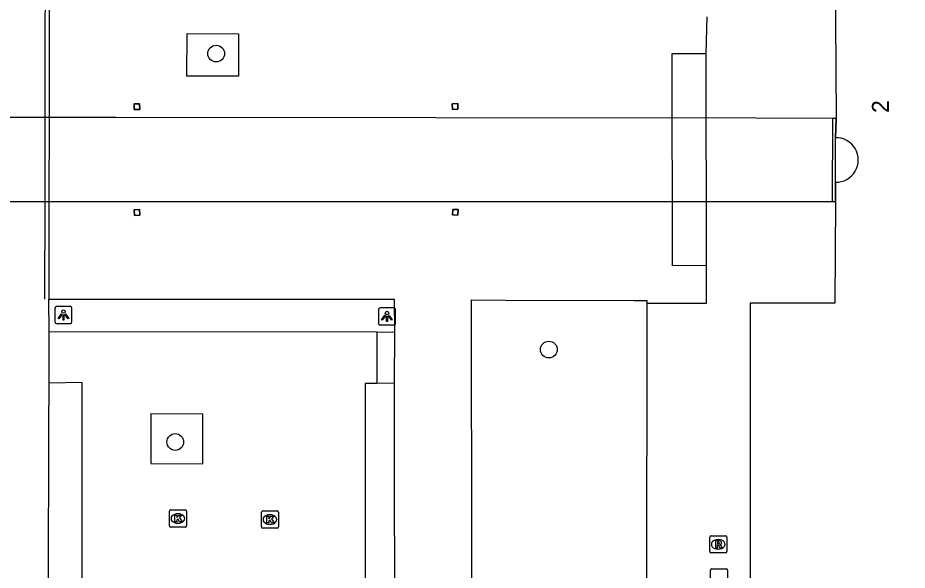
# Model space of a CAD drawing. Extents: x 161477 to 163040, y 383680 to 384868.
# Drawn here: x 161812.2 to 161864.2, y 384291 to 384323.3 of the extents above; entities that cross this region are included whole.
import ezdxf

# ---------------------------------------------------------------- set-up
doc = ezdxf.new("R2010")
doc.units = 0
for name, color, linetype in [('IMGEO_Boom', 7, 'Continuous'), ('IMGEO_Dek', 7, 'Continuous'), ('IMGEO_Kolk', 7, 'Continuous'), ('IMGEO_Lichtpunt', 7, 'Continuous'), ('IMGEO_Lijnafwatering', 7, 'Continuous'), ('IMGEO_Pand', 7, 'Continuous'), ('IMGEO_Pand_nummerreeks', 7, 'Continuous'), ('IMGEO_Parkeervlak_open', 7, 'Continuous'), ('IMGEO_Pijler', 7, 'Continuous'), ('IMGEO_Rijbaan_lokaal_open', 7, 'Continuous'), ('IMGEO_Rioolput', 7, 'Continuous'), ('IMGEO_Voetpad_gesloten', 7, 'Continuous'), ('IMGEO_Voetpad_op_trap', 7, 'Continuous'), ('IMGEO_Voetpad_open', 7, 'Continuous')]:
    doc.layers.add(name, color=color, linetype=linetype)

msp = doc.modelspace()

# ---------------------------------------------------------------- linework, layer by layer
at = {"layer": 'IMGEO_Boom'}
for centre in [(161823.823, 384321.172), (161843.275, 384303.878), (161821.432, 384298.478)]:
    msp.add_circle(centre, 0.489, dxfattribs=at)
at = {"layer": 'IMGEO_Dek'}
msp.add_lwpolyline([(161859.88, 384317.389), (161855.377, 384317.394), (161817.96, 384317.433), (161817.483, 384317.433), (161815.892, 384317.434), (161810.287, 384317.441), (161807.922, 384317.443), (161801.84, 384317.449), (161797.149, 384317.454), (161796.557, 384317.455), (161796.614, 384312.532), (161797.345, 384312.53), (161799.896, 384312.527), (161807.923, 384312.527), (161808.422, 384312.528), (161810.306, 384312.528), (161815.872, 384312.528), (161817.492, 384312.528), (161817.958, 384312.528), (161855.375, 384312.529), (161859.867, 384312.53)], close=True, dxfattribs=at)
at = {"layer": 'IMGEO_Kolk'}
for p, q in [((161821.088, 384293.582), (161821.088, 384294.434)), ((161821.163, 384294.508), (161822.015, 384294.508)), ((161822.089, 384294.434), (161822.089, 384293.582)), ((161826.541, 384294.447), (161827.393, 384294.447)), ((161821.576, 384294.288), (161821.601, 384294.288)), ((161826.466, 384293.521), (161826.466, 384294.373)), ((161826.954, 384294.227), (161826.979, 384294.227)), ((161827.467, 384294.373), (161827.467, 384293.521)), ((161822.015, 384293.508), (161821.163, 384293.508)), ((161821.599, 384293.728), (161821.574, 384293.728)), ((161827.393, 384293.447), (161826.541, 384293.447)), ((161826.977, 384293.667), (161826.952, 384293.667))]:
    msp.add_line(p, q, dxfattribs=at)
for points in [[(161821.088, 384293.582), (161821.088, 384294.434)], [(161821.163, 384294.508), (161822.015, 384294.508)], [(161822.089, 384294.434), (161822.089, 384293.582)], [(161826.541, 384294.447), (161827.393, 384294.447)], [(161821.409, 384294.208), (161821.532, 384294.208), (161821.532, 384294.057), (161821.662, 384294.208), (161821.826, 384294.208), (161821.68, 384294.057), (161821.833, 384293.808), (161821.681, 384293.808), (161821.596, 384293.972), (161821.532, 384293.905), (161821.532, 384293.808), (161821.409, 384293.808), (161821.409, 384294.208)], [(161826.466, 384293.521), (161826.466, 384294.373)], [(161826.787, 384294.147), (161826.91, 384294.147), (161826.91, 384293.996), (161827.04, 384294.147), (161827.204, 384294.147), (161827.058, 384293.996), (161827.211, 384293.747), (161827.059, 384293.747), (161826.974, 384293.911), (161826.91, 384293.844), (161826.91, 384293.747), (161826.787, 384293.747), (161826.787, 384294.147)], [(161827.467, 384294.373), (161827.467, 384293.521)], [(161822.015, 384293.508), (161821.163, 384293.508)], [(161827.393, 384293.447), (161826.541, 384293.447)]]:
    msp.add_lwpolyline(points, dxfattribs=at)
for centre, start, end in [((161821.165, 384294.432), 91.552, 178.448), ((161821.165, 384294.432), 91.552, 178.448), ((161822.013, 384294.432), 1.552, 88.448), ((161822.013, 384294.432), 1.552, 88.448), ((161826.543, 384294.371), 91.552, 178.448), ((161826.543, 384294.371), 91.552, 178.448), ((161827.391, 384294.371), 1.552, 88.448), ((161827.391, 384294.371), 1.552, 88.448), ((161821.165, 384293.584), 181.552, 268.448), ((161821.165, 384293.584), 181.552, 268.448), ((161822.013, 384293.584), 271.552, 358.448), ((161822.013, 384293.584), 271.552, 358.448), ((161826.543, 384293.523), 181.552, 268.448), ((161826.543, 384293.523), 181.552, 268.448), ((161827.391, 384293.523), 271.552, 358.448), ((161827.391, 384293.523), 271.552, 358.448)]:
    msp.add_arc(centre, 0.0765, start, end, dxfattribs=at)
for centre, major_axis, ratio, start_param, end_param in [((161821.575, 384294.008), (-0.387, 0.002), 0.722429, 4.712389, 7.853982), ((161821.6, 384294.008), (-0.39, 0.002), 0.717154, 1.570796, 4.712389), ((161826.953, 384293.947), (-0.387, 0.002), 0.722429, 4.712389, 7.853982), ((161826.978, 384293.947), (-0.39, 0.002), 0.717154, 1.570796, 4.712389)]:
    msp.add_ellipse(centre, major_axis=major_axis, ratio=ratio, start_param=start_param, end_param=end_param, dxfattribs=at)
at = {"layer": 'IMGEO_Lichtpunt'}
for p, q in [((161815.298, 384306.394), (161814.49, 384306.394)), ((161815.298, 384306.394), (161814.49, 384306.394)), ((161814.396, 384306.299), (161814.396, 384305.492)), ((161814.396, 384306.299), (161814.396, 384305.492)), ((161815.392, 384305.492), (161815.392, 384306.299)), ((161815.392, 384305.492), (161815.392, 384306.299)), ((161833.313, 384306.216), (161833.313, 384305.409)), ((161833.313, 384306.216), (161833.313, 384305.409)), ((161834.215, 384306.311), (161833.407, 384306.311)), ((161834.215, 384306.311), (161833.407, 384306.311)), ((161834.309, 384305.409), (161834.309, 384306.216)), ((161834.309, 384305.409), (161834.309, 384306.216)), ((161814.49, 384305.398), (161815.298, 384305.398)), ((161814.49, 384305.398), (161815.298, 384305.398)), ((161833.407, 384305.315), (161834.215, 384305.315)), ((161833.407, 384305.315), (161834.215, 384305.315))]:
    msp.add_line(p, q, dxfattribs=at)
for points in [[(161814.77, 384305.963), (161814.809, 384305.935), (161814.621, 384305.673), (161814.583, 384305.7), (161814.77, 384305.963)], [(161814.872, 384305.915), (161814.919, 384305.915), (161814.919, 384305.593), (161814.872, 384305.593), (161814.872, 384305.915)], [(161814.982, 384305.935), (161815.02, 384305.962), (161815.207, 384305.7), (161815.168, 384305.672), (161814.982, 384305.935)], [(161833.687, 384305.88), (161833.726, 384305.852), (161833.538, 384305.59), (161833.5, 384305.617), (161833.687, 384305.88)], [(161833.789, 384305.832), (161833.836, 384305.832), (161833.836, 384305.51), (161833.789, 384305.51), (161833.789, 384305.832)], [(161833.899, 384305.852), (161833.937, 384305.879), (161834.124, 384305.617), (161834.085, 384305.589), (161833.899, 384305.852)]]:
    msp.add_lwpolyline(points, dxfattribs=at)
for centre in [(161814.895, 384306.097), (161833.812, 384306.014)]:
    msp.add_circle(centre, 0.0994, dxfattribs=at)
for centre, start, end in [((161814.49, 384306.299), 90, 180), ((161814.49, 384306.299), 90, 180), ((161815.298, 384306.299), 0, 90), ((161815.298, 384306.299), 0, 90), ((161833.407, 384306.216), 90, 180), ((161833.407, 384306.216), 90, 180), ((161834.215, 384306.216), 0, 90), ((161834.215, 384306.216), 0, 90), ((161814.49, 384305.492), 180, 270), ((161814.49, 384305.492), 180, 270), ((161815.298, 384305.492), 270, 0), ((161815.298, 384305.492), 270, 360), ((161833.407, 384305.409), 180, 270), ((161833.407, 384305.409), 180, 270), ((161834.215, 384305.409), 270, 0), ((161834.215, 384305.409), 270, 360)]:
    msp.add_arc(centre, 0.0946, start, end, dxfattribs=at)
at = {"layer": 'IMGEO_Lijnafwatering'}
for points in [[(161813.824, 384317.437), (161813.835, 384329.719)], [(161813.819, 384312.528), (161813.824, 384317.437)], [(161813.814, 384306.819), (161813.819, 384312.528)]]:
    msp.add_lwpolyline(points, dxfattribs=at)
at = {"layer": 'IMGEO_Pand'}
for points in [[(161852.559, 384329.203), (161860.001, 384329.128), (161860.002, 384328.971), (161860.071, 384317.389), (161860.03, 384316.258)], [(161860.03, 384313.658), (161860.049, 384312.53), (161860.003, 384306.592), (161855.053, 384306.595), (161855.033, 384267.359)]]:
    msp.add_lwpolyline(points, dxfattribs=at)
msp.add_arc((161860.068, 384314.958), 1.301, 268.3067, 91.6933, dxfattribs=at)
at = {"layer": 'IMGEO_Parkeervlak_open'}
for points in [[(161814.057, 384304.937), (161833.227, 384304.914)], [(161814.017, 384269.739), (161815.984, 384269.764), (161815.992, 384301.962), (161814.049, 384301.923)], [(161833.222, 384301.901), (161832.538, 384301.901), (161832.535, 384269.792), (161833.234, 384269.806)], [(161823.049, 384300.107), (161820.005, 384300.13), (161820.005, 384297.224), (161823.034, 384297.204), (161823.049, 384300.107)]]:
    msp.add_lwpolyline(points, dxfattribs=at)
at = {"layer": 'IMGEO_Pijler'}
for points in [[(161819.342, 384318.246), (161819.028, 384318.238), (161819.036, 384317.908), (161819.35, 384317.916)], [(161837.949, 384318.249), (161837.628, 384318.234), (161837.643, 384317.905), (161837.964, 384317.92)], [(161837.975, 384312.055), (161837.667, 384312.073), (161837.648, 384311.744), (161837.956, 384311.726)], [(161819.339, 384312.06), (161819.036, 384312.041), (161819.056, 384311.711), (161819.359, 384311.73)]]:
    msp.add_lwpolyline(points, close=True, dxfattribs=at)
at = {"layer": 'IMGEO_Rijbaan_lokaal_open'}
for points in [[(161814.035, 384329.719), (161814.06, 384323.352), (161814.051, 384317.437), (161814.043, 384312.528), (161814.034, 384306.822)], [(161814.057, 384304.937), (161814.034, 384306.822)], [(161814.049, 384301.923), (161814.057, 384304.937)], [(161814.017, 384269.739), (161814.02, 384280.045), (161814.015, 384290.015), (161814.031, 384299.293), (161814.049, 384301.923)]]:
    msp.add_lwpolyline(points, dxfattribs=at)
at = {"layer": 'IMGEO_Rioolput'}
for p, q in [((161852.682, 384292.073), (161852.682, 384292.925)), ((161852.757, 384292.999), (161853.609, 384292.999)), ((161853.683, 384292.925), (161853.683, 384292.073)), ((161853.17, 384292.779), (161853.195, 384292.779)), ((161853.609, 384291.999), (161852.757, 384291.999)), ((161853.193, 384292.219), (161853.168, 384292.219)), ((161852.725, 384290.135), (161852.725, 384290.987)), ((161852.8, 384291.061), (161853.652, 384291.061)), ((161853.726, 384290.987), (161853.726, 384290.135))]:
    msp.add_line(p, q, dxfattribs=at)
for points in [[(161852.682, 384292.073), (161852.682, 384292.925)], [(161852.757, 384292.999), (161853.609, 384292.999)], [(161853.683, 384292.925), (161853.683, 384292.073)], [(161853.271, 384292.697), (161853.019, 384292.699), (161853.019, 384292.299)], [(161853.019, 384292.299), (161853.143, 384292.299), (161853.143, 384292.461), (161853.154, 384292.461)], [(161853.197, 384292.618), (161853.143, 384292.618), (161853.143, 384292.537)], [(161853.143, 384292.537), (161853.195, 384292.537)], [(161853.201, 384292.432), (161853.272, 384292.299), (161853.412, 384292.299), (161853.347, 384292.425)], [(161853.609, 384291.999), (161852.757, 384291.999)], [(161852.725, 384290.135), (161852.725, 384290.987)], [(161852.8, 384291.061), (161853.652, 384291.061)], [(161853.726, 384290.987), (161853.726, 384290.135)]]:
    msp.add_lwpolyline(points, dxfattribs=at)
for centre, radius, start, end in [((161852.759, 384292.923), 0.0765, 91.552, 178.448), ((161852.759, 384292.923), 0.0765, 91.552, 178.448), ((161853.607, 384292.923), 0.0765, 1.552, 88.448), ((161853.607, 384292.923), 0.0765, 1.552, 88.448), ((161853.153, 384292.408), 0.0533, 26.0293, 88.6989), ((161853.179, 384292.726), 0.19, 274.7715, 282.9687), ((161853.203, 384292.522), 0.0964, 77.0061, 93.1865), ((161853.217, 384292.579), 0.0378, 276.6634, 79.6772), ((161853.27, 384292.587), 0.109, 350.3612, 89.416), ((161853.268, 384292.587), 0.112, 277.5842, 350.9817), ((161853.252, 384292.372), 0.108, 29.5134, 73.7905), ((161852.759, 384292.075), 0.0765, 181.552, 268.448), ((161852.759, 384292.075), 0.0765, 181.552, 268.448), ((161853.607, 384292.075), 0.0765, 271.552, 358.448), ((161853.607, 384292.075), 0.0765, 271.552, 358.448), ((161852.802, 384290.985), 0.0765, 91.552, 178.448), ((161852.802, 384290.985), 0.0765, 91.552, 178.448), ((161853.65, 384290.985), 0.0765, 1.552, 88.448), ((161853.65, 384290.985), 0.0765, 1.552, 88.448)]:
    msp.add_arc(centre, radius, start, end, dxfattribs=at)
for centre, major_axis, ratio, start_param, end_param in [((161853.169, 384292.499), (-0.387, 0.002), 0.722429, 4.712389, 7.853982), ((161853.194, 384292.499), (-0.39, 0.002), 0.717154, 1.570796, 4.712389)]:
    msp.add_ellipse(centre, major_axis=major_axis, ratio=ratio, start_param=start_param, end_param=end_param, dxfattribs=at)
at = {"layer": 'IMGEO_Voetpad_gesloten'}
for points in [[(161860.071, 384317.389), (161859.88, 384317.389), (161855.377, 384317.394), (161817.96, 384317.433), (161817.483, 384317.433), (161815.892, 384317.434), (161810.287, 384317.441)], [(161810.306, 384312.528), (161815.872, 384312.528), (161817.492, 384312.528), (161817.958, 384312.528), (161855.375, 384312.529), (161859.867, 384312.53), (161860.049, 384312.53), (161860.03, 384313.658), (161860.03, 384316.258), (161860.071, 384317.389)]]:
    msp.add_lwpolyline(points, dxfattribs=at)
at = {"layer": 'IMGEO_Voetpad_op_trap'}
for points in [[(161833.227, 384304.914), (161833.222, 384301.901)], [(161833.227, 384304.914), (161834.252, 384304.905)], [(161834.237, 384301.912), (161833.222, 384301.901)]]:
    msp.add_lwpolyline(points, dxfattribs=at)
at = {"layer": 'IMGEO_Voetpad_open'}
for points in [[(161852.474, 384321.173), (161852.533, 384323.314)], [(161825.128, 384319.85), (161822.115, 384319.849), (161822.119, 384322.342), (161825.136, 384322.337), (161825.128, 384319.85)], [(161852.501, 384308.788), (161850.512, 384308.768), (161850.512, 384309.258), (161850.506, 384312.529), (161850.496, 384317.399), (161850.489, 384321.17), (161852.474, 384321.173)], [(161852.501, 384308.788), (161852.493, 384312.529), (161852.482, 384317.397), (161852.474, 384321.173)], [(161819.35, 384317.916), (161819.036, 384317.908), (161819.028, 384318.238), (161819.342, 384318.246), (161819.35, 384317.916)], [(161837.964, 384317.92), (161837.643, 384317.905), (161837.628, 384318.234), (161837.949, 384318.249), (161837.964, 384317.92)], [(161837.956, 384311.726), (161837.648, 384311.744), (161837.667, 384312.073), (161837.975, 384312.055), (161837.956, 384311.726)], [(161819.359, 384311.73), (161819.056, 384311.711), (161819.036, 384312.041), (161819.339, 384312.06), (161819.359, 384311.73)], [(161848.999, 384306.584), (161852.496, 384306.589), (161852.501, 384308.788)], [(161814.034, 384306.822), (161834.233, 384306.821), (161834.252, 384304.905)], [(161864.233, 384261.629), (161864.127, 384261.629), (161864.088, 384256.647), (161861.058, 384256.647), (161859.948, 384256.647), (161840.921, 384256.647), (161838.799, 384256.777), (161838.797, 384257.441), (161838.768, 384275.095), (161838.765, 384291.613), (161838.752, 384306.78), (161840.752, 384306.775), (161848.275, 384306.754), (161848.999, 384306.752), (161848.999, 384306.584)], [(161848.999, 384306.584), (161848.995, 384288.764), (161849.004, 384267.346), (161854.547, 384267.358), (161855.033, 384267.359)], [(161834.252, 384304.905), (161834.237, 384301.912)], [(161834.237, 384301.912), (161834.25, 384284.041), (161834.244, 384269.796)]]:
    msp.add_lwpolyline(points, dxfattribs=at)

# ---------------------------------------------------------------- texts
at = {"layer": 'IMGEO_Pand_nummerreeks'}
msp.add_text('2', height=1, rotation=89.9601, dxfattribs=at).set_placement((161863.168, 384317.704))

doc.saveas('drawing.dxf')
